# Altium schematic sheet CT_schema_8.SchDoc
size 287 x 160 mm
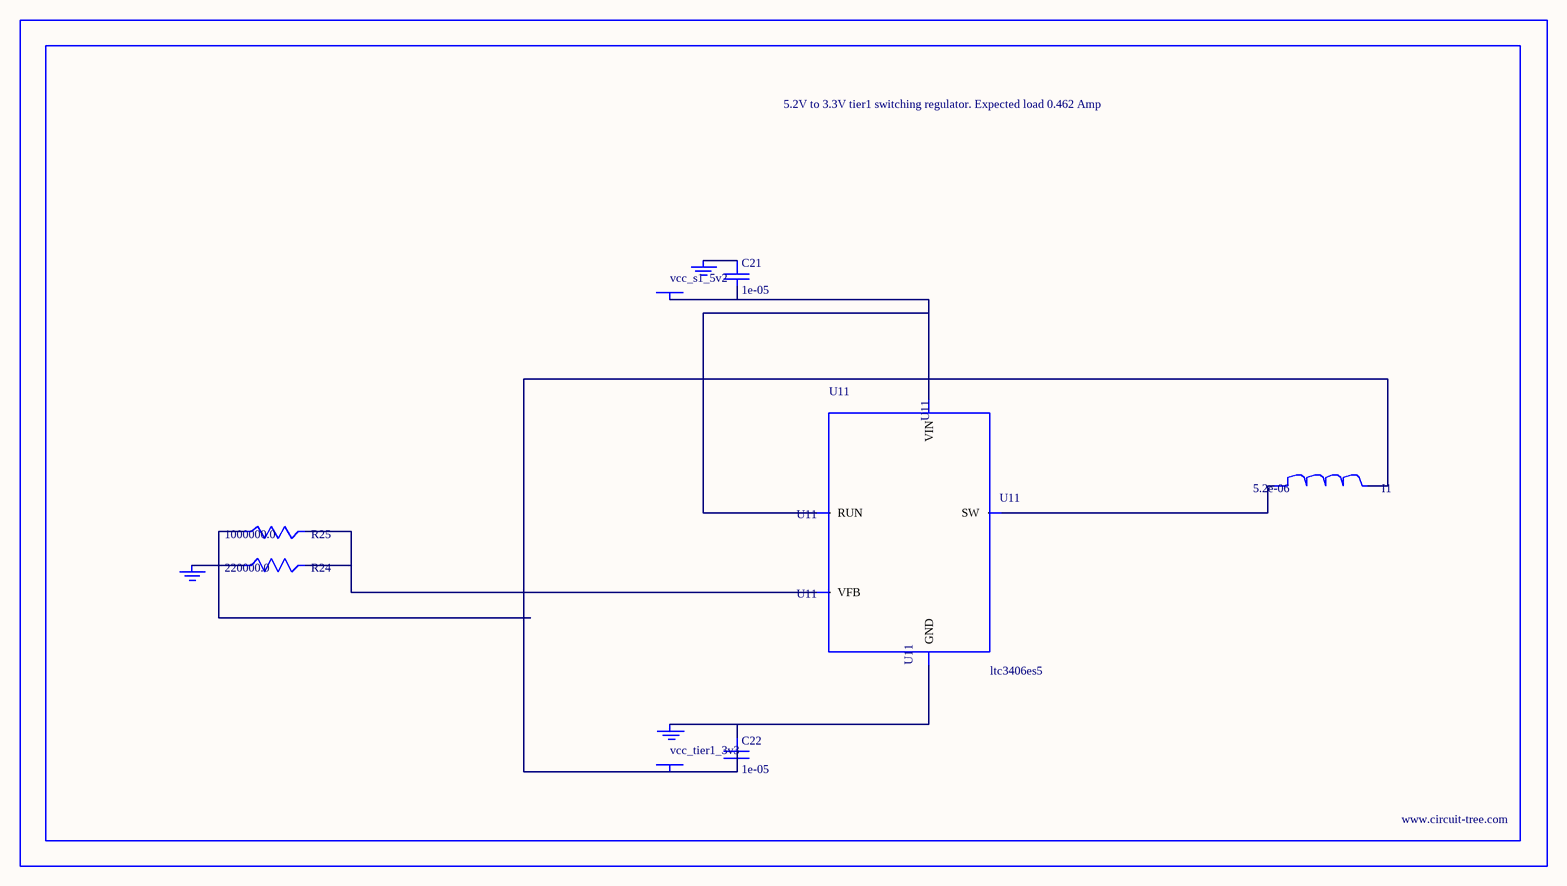
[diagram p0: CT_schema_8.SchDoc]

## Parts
BORDER7  (no value)
C21  1e-05  [C0805]
C22  1e-05  [C0805]
GND_INSTANCE_7_0  (no value)
GND_INSTANCE_7_1  (no value)
GND_INSTANCE_7_2  (no value)
I1  5.2e-06  [DR1040]
POWER_INSTANCE_7_0  vcc_tier1_3v3
POWER_INSTANCE_7_1  vcc_s1_5v2
R24  220000.0  [R0603]
R25  1000000.0  [R0603]
U11  ltc3406es5  [TSOT-23-5]

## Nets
NetC21_1: C21.1 GND_INSTANCE_7_1.0(GND)
NetC21_2: C21.2 POWER_INSTANCE_7_1.0(PWR) U11.1(RUN) U11.4(VIN)
NetC22_1: C22.1 GND_INSTANCE_7_0.0(GND) U11.2(GND)
NetC22_2: C22.2 I1.2 POWER_INSTANCE_7_0.0(PWR) R25.1
NetGND_INSTANCE_7_2_0: GND_INSTANCE_7_2.0(GND) R24.1
NetI1_1: I1.1 U11.3(SW)
NetR24_2: R24.2 R25.2 U11.5(VFB)

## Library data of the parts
BORDER7 = BORDER_PAGE7
C21 C22 = C0805C106K8RACTU
GND_INSTANCE_7_0-GND_INSTANCE_7_2 = GND
I1 = DR1040-5R2-R
POWER_INSTANCE_7_0 POWER_INSTANCE_7_1 = PWR
R24 = RC0603JR-07220KL
R25 = RC0603JR-071ML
